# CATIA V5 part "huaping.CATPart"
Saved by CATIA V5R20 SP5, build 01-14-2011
Part number: 花瓶
Material "Fabric 4": density 200 kg/m3
Material "Wallpaper Strip 2": density 2120 kg/m3, Young's modulus 2.56e+10 Pa, Poisson ratio 0.22
Bounding box of the stored display mesh (mm): x -41.18 to 41.18, y -41.197 to 41.155, z 0 to 100
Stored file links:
  E:\180522132\Part2.CATPart
  C:\Program Files\Dassault Systemes\B20\intel_a\startup\materials\Catalog.CATMaterial
  C:\Program Files\Dassault Systemes\B20\intel_a\startup\materials\blue_env_512x512.jpg
  C:\Program Files\Dassault Systemes\B20\intel_a\startup\materials\lead.jpg
  C:\Program Files\Dassault Systemes\B20\intel_a\startup\materials\eroded_metal_1.jpg
  C:\Program Files\Dassault Systemes\B20\intel_a\startup\materials\brushed_metal2.jpg
  C:\Program Files\Dassault Systemes\B20\intel_a\startup\materials\blue_fabric_02.jpg
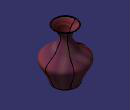
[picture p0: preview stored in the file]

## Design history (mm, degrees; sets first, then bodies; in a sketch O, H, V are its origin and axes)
Body1 (main body), material "Fabric 4"
  Plane1: linked copy from another document
  Plane2: type Offset, RefPlane xy-plane, Offset 20
  Plane3: type Offset, RefPlane Plane2, Offset 20
  Plane4: type Offset, RefPlane Plane3, Offset 20
  Plane5: type Offset, RefPlane Plane4, Offset 20
  Plane6: type Offset, RefPlane Plane5, Offset 20
  Sketch1 on Plane1, origin (0, 0, 0), H (1, 0, 0), V (0, 1, 0)
    circle A1 centre (0, 0) radius 20
  Sketch2 on Plane5, origin (0, 0, 80), H (1, 0, 0), V (0, 1, 0)
  Sketch3 on Plane4, origin (0, 0, 60), H (1, 0, 0), V (0, 1, 0)
  Sketch4 on Plane2, origin (0, 0, 20), H (1, 0, 0), V (0, 1, 0)
  Sketch5 on Plane5, origin (0, 0, 80), H (1, 0, 0), V (0, 1, 0)
  Sketch6 on Plane6, origin (0, 0, 100), H (1, 0, 0), V (0, 1, 0)
    circle A1 centre (0, 0) radius 22.3607
  Sketch7 on Plane5, origin (0, 0, 80), H (1, 0, 0), V (0, 1, 0)
    point P1 (90, 0)
    circle A1 centre (0, 0) radius 10
    coincidence: P1 H
  Sketch8 on Plane4, origin (0, 0, 60), H (1, 0, 0), V (0, 1, 0)
    circle A1 centre (0, 0) radius 20
  Sketch9 on Plane3, origin (0, 0, 40), H (1, 0, 0), V (0, 1, 0)
    circle A1 centre (0, 0) radius 41.2311
  Sketch10 on Plane2, origin (0, 0, 20), H (1, 0, 0), V (0, 1, 0)
    circle A1 centre (0, 0) radius 31.6228
    construction line L1 through (0, 0) direction (1, 0)
  Sketch11 on Plane1, origin (0, 0, 0), H (1, 0, 0), V (0, 1, 0)
    circle A1 centre (0, 0) radius 23.5
  Loft1: solid, Sections (Sketch6; Sketch7; Sketch8; Sketch9; Sketch10; Sketch11)
  Shell1: ExtOffset 0, IntOffset 1
  Shell2: ExtOffset 0, Face face of Loft1, IntOffset 1
Body2
  Sketch12 on yz-plane, origin (0, 0, 0), H (0, 1, 0), V (0, 0, 1)
    axis line L1 (0, 109.9957) -> (0, -8.9151)
    point P1 (0, 109.9957)
    point P3 (0, 39.8688)
    line L2 (0, 39.8688) -> (39.4903, 39.8688)
    line L3 (39.4903, 39.8688) -> (22.5305, 1.8949)
    line L4 (22.5305, 1.8949) -> (0, 1.8949)
    point P6 (0, 1.8949)
    coincidence: P1 V, P3 L1, P6 L1
    vertical: L1 V
    horizontal: L2 H, L4 H
  Shaft1: profile Sketch12, axis Sketch12.L1, angle 360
